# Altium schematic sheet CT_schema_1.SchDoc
size 641 x 498 mm
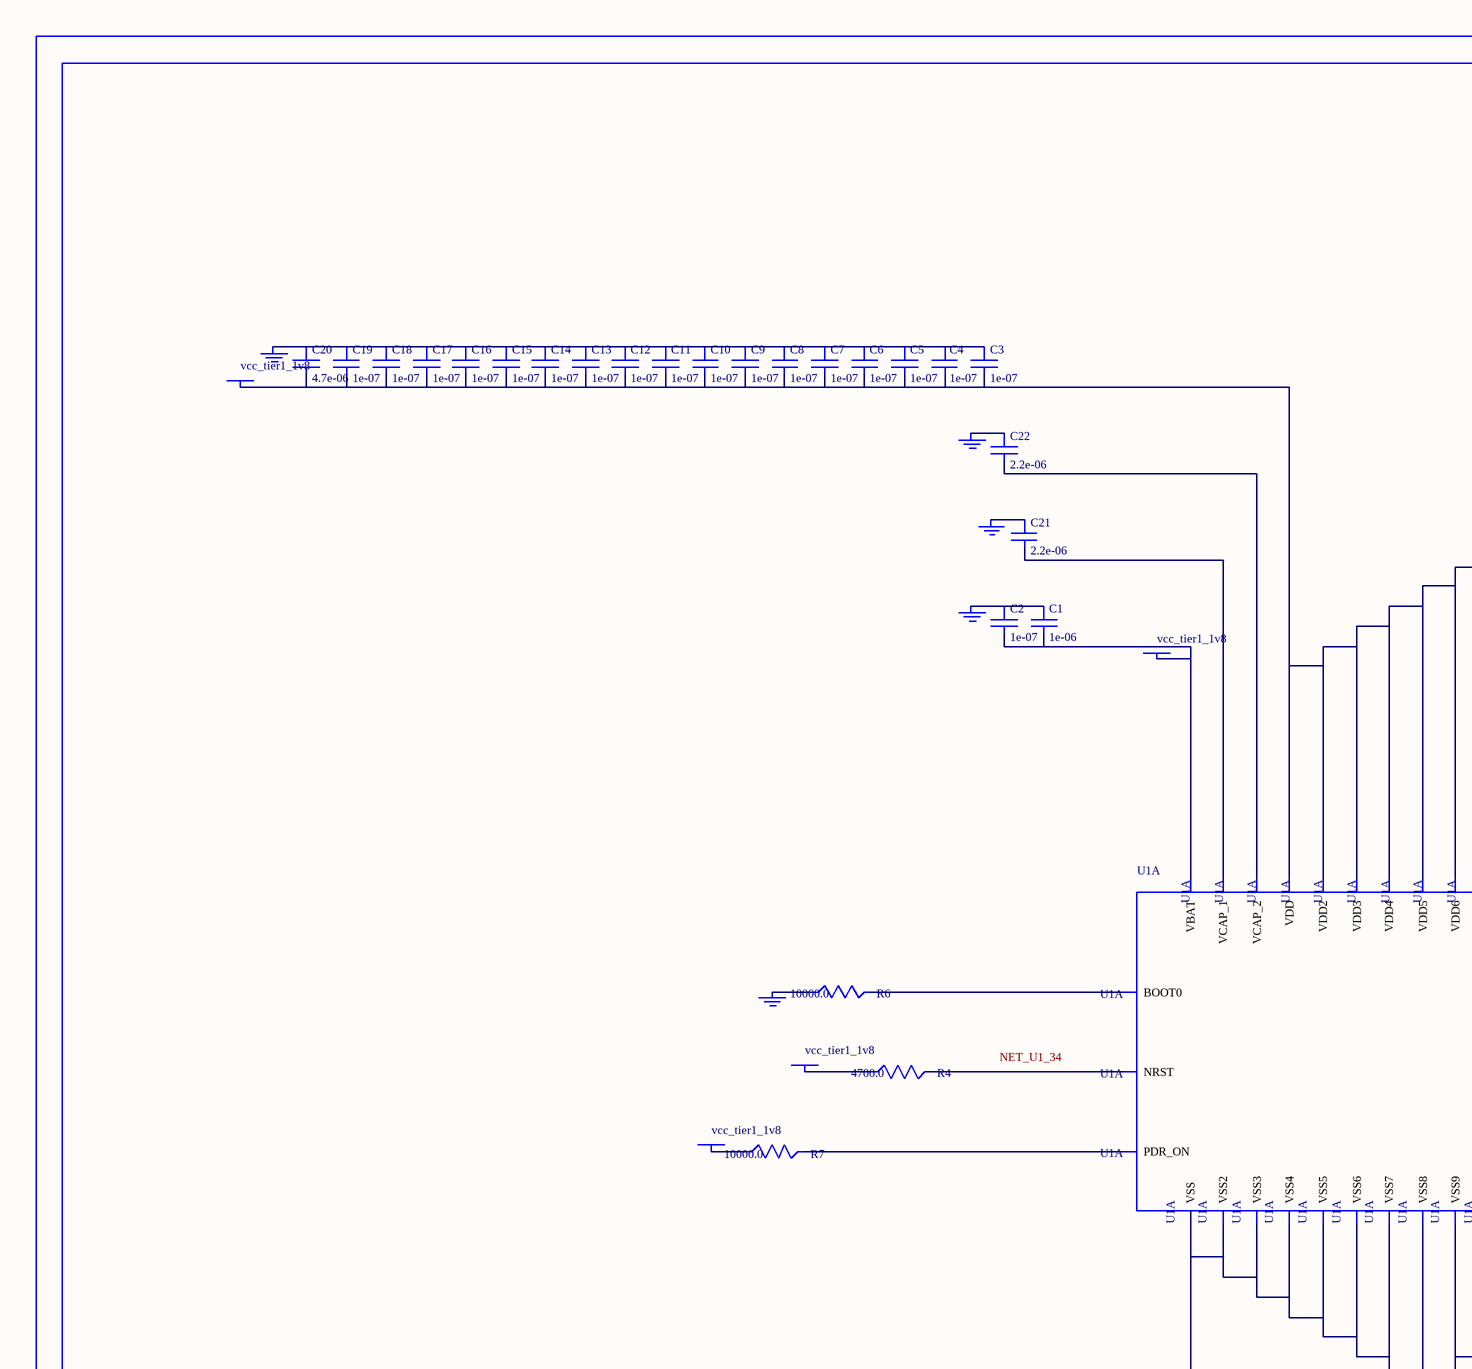
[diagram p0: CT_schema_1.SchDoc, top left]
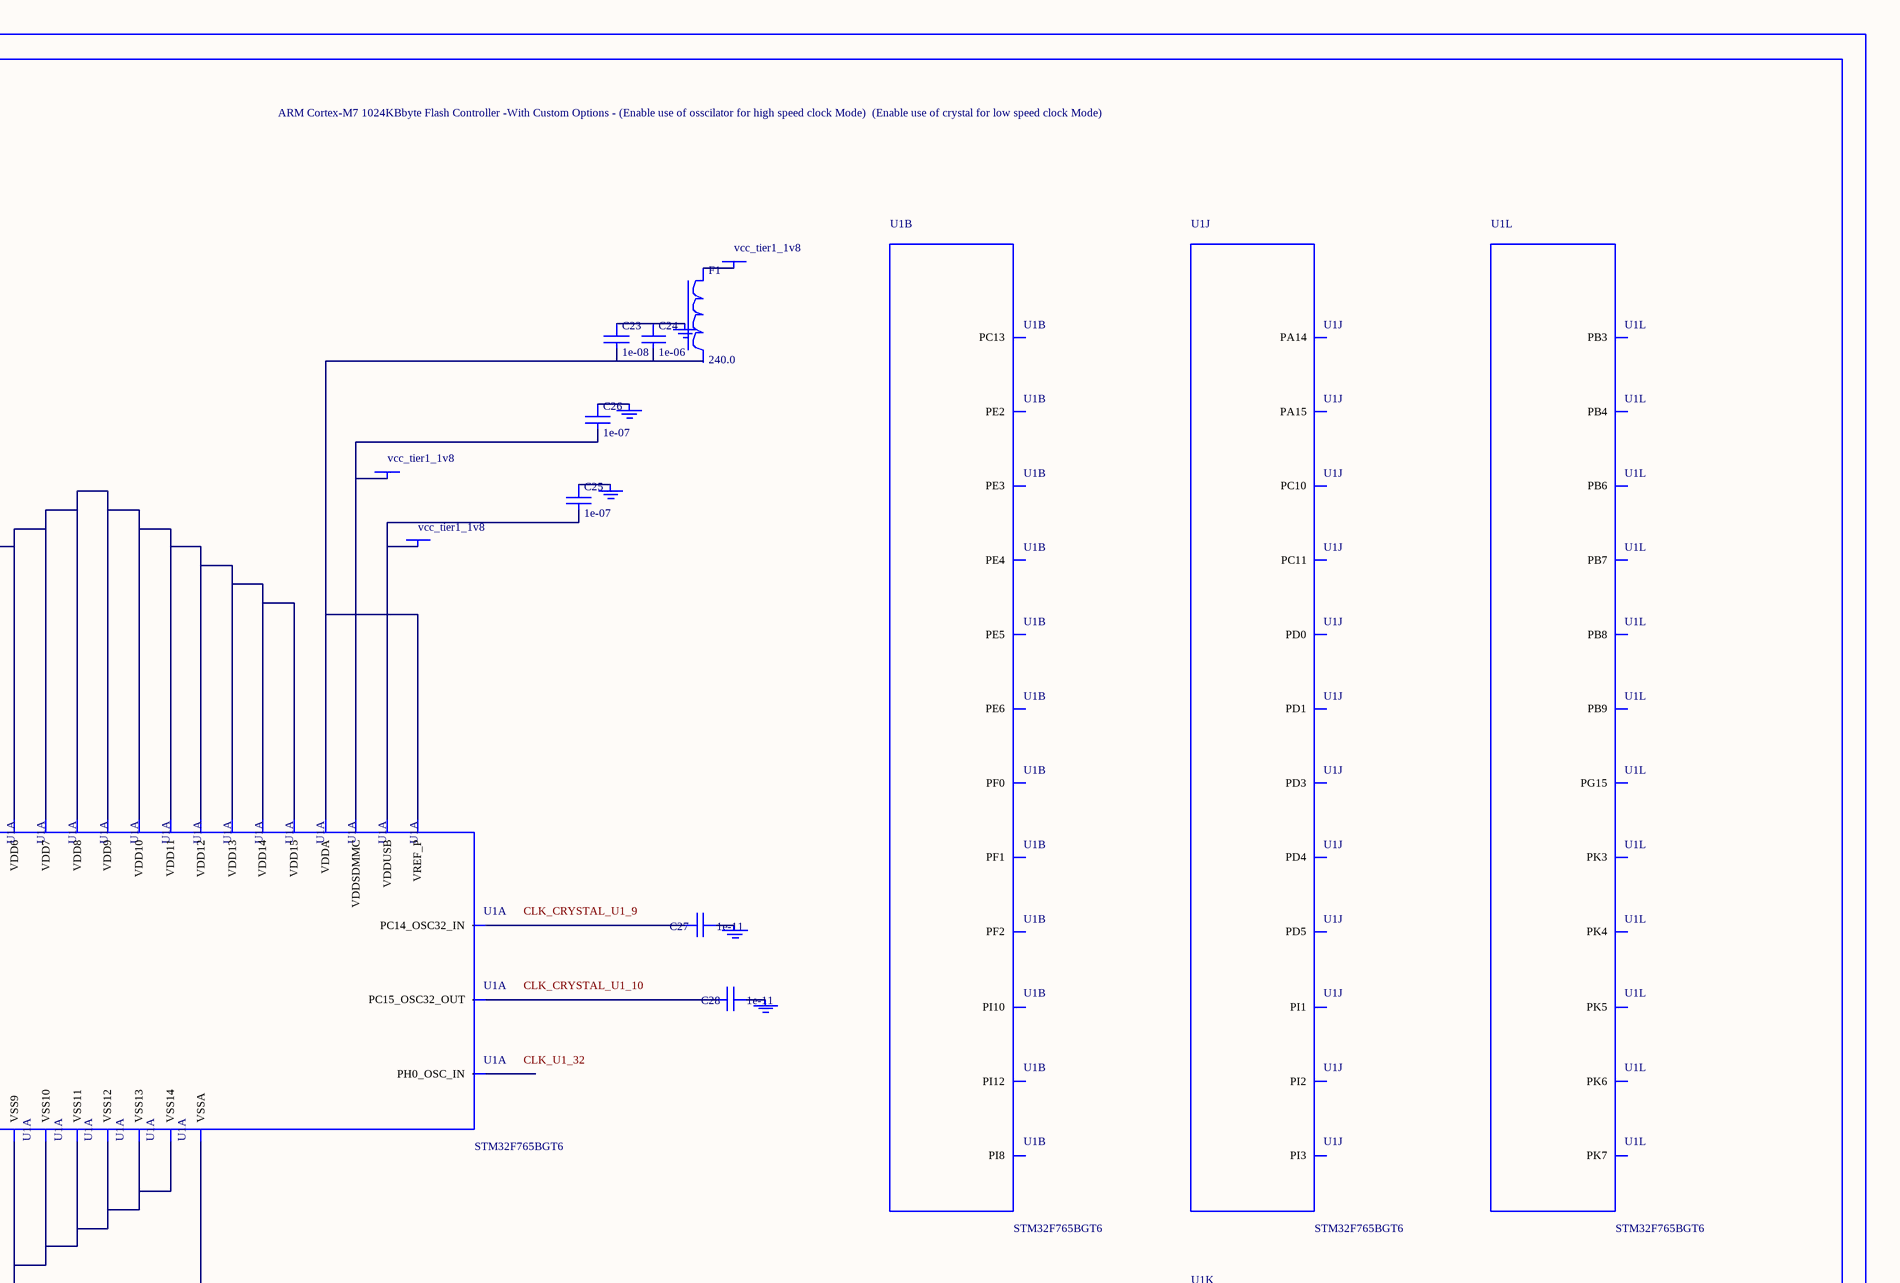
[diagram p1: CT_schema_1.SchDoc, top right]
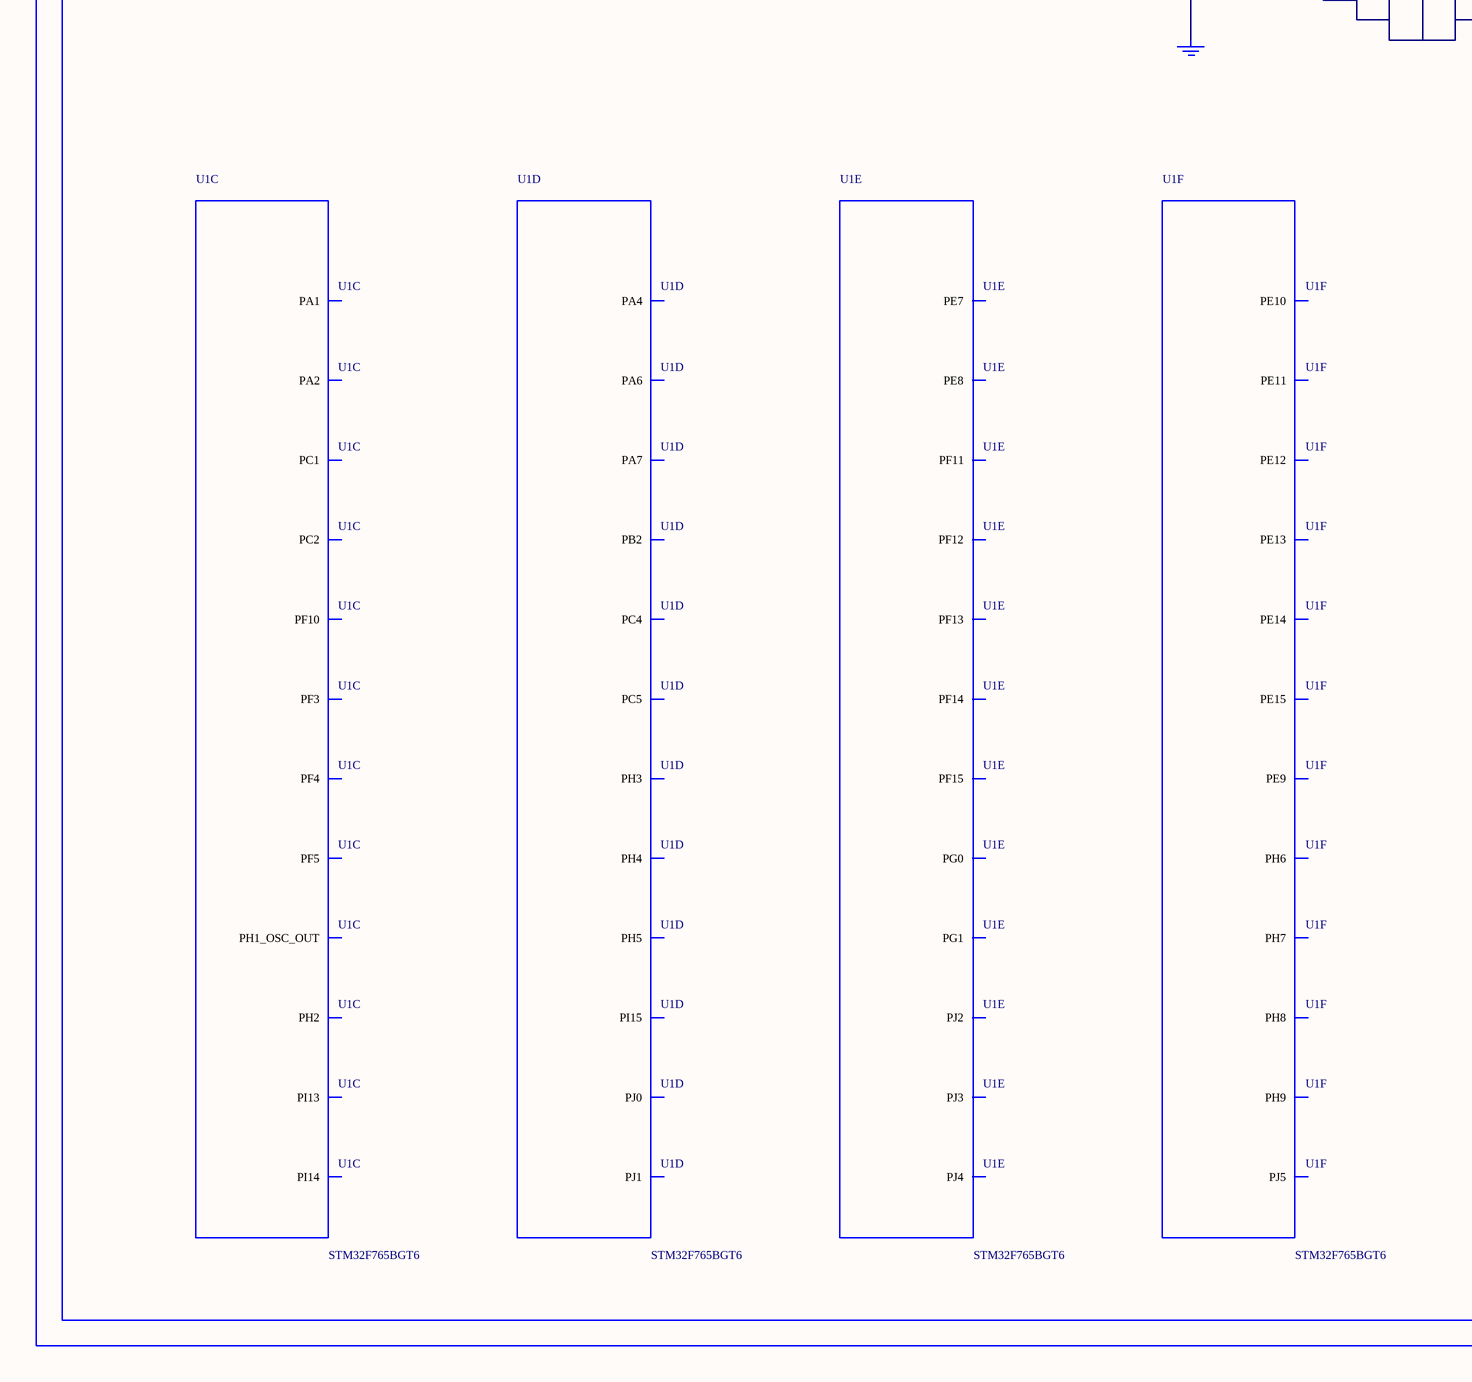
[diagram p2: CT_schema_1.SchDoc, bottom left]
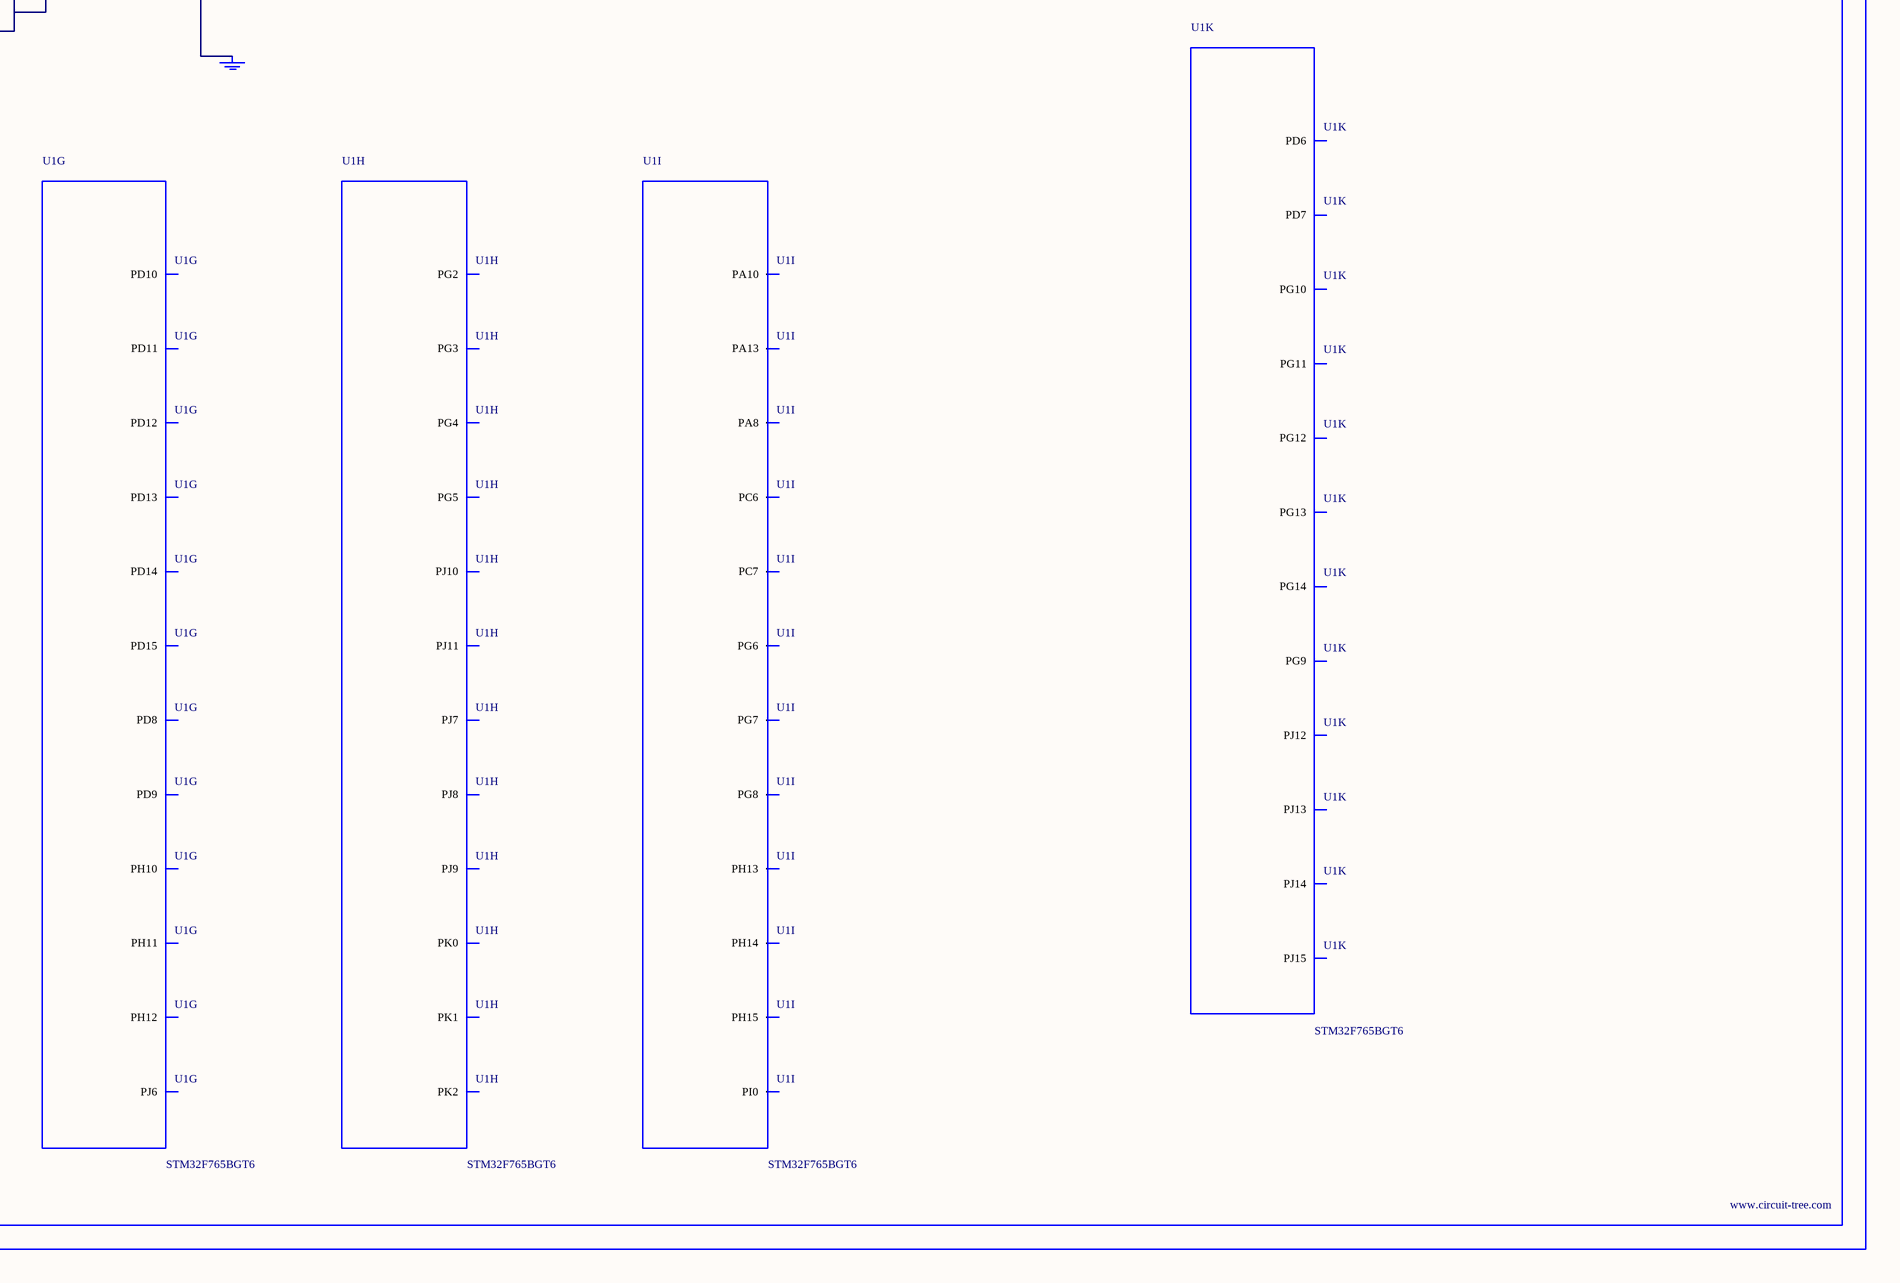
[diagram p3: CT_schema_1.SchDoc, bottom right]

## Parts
BORDER0  (no value)
C1  1e-06  [C0603]
C2  1e-07  [C0603]
C3  1e-07  [C0603]
C4  1e-07  [C0603]
C5  1e-07  [C0603]
C6  1e-07  [C0603]
C7  1e-07  [C0603]
C8  1e-07  [C0603]
C9  1e-07  [C0603]
C10  1e-07  [C0603]
C11  1e-07  [C0603]
C12  1e-07  [C0603]
C13  1e-07  [C0603]
C14  1e-07  [C0603]
C15  1e-07  [C0603]
C16  1e-07  [C0603]
C17  1e-07  [C0603]
C18  1e-07  [C0603]
C19  1e-07  [C0603]
C20  4.7e-06  [C0603]
C21  2.2e-06  [C0603]
C22  2.2e-06  [C0603]
C23  1e-08  [C0603]
C24  1e-06  [C0603]
C25  1e-07  [C0603]
C26  1e-07  [C0603]
C27  1e-11  [C0402]
C28  1e-11  [C0402]
F1  240.0  [L0603]
GND_INSTANCE_0_0  (no value)
GND_INSTANCE_0_1  (no value)
GND_INSTANCE_0_2  (no value)
GND_INSTANCE_0_3  (no value)
GND_INSTANCE_0_4  (no value)
GND_INSTANCE_0_5  (no value)
GND_INSTANCE_0_6  (no value)
GND_INSTANCE_0_7  (no value)
GND_INSTANCE_0_8  (no value)
GND_INSTANCE_0_9  (no value)
GND_INSTANCE_0_10  (no value)
GND_INSTANCE_0_11  (no value)
POWER_INSTANCE_0_0  vcc_tier1_1v8
POWER_INSTANCE_0_1  vcc_tier1_1v8
POWER_INSTANCE_0_2  vcc_tier1_1v8
POWER_INSTANCE_0_3  vcc_tier1_1v8
POWER_INSTANCE_0_4  vcc_tier1_1v8
POWER_INSTANCE_0_5  vcc_tier1_1v8
POWER_INSTANCE_0_6  vcc_tier1_1v8
R4  4700.0  [R0603]
R6  10000.0  [R0603]
R7  10000.0  [R0603]
U1  STM32F765BGT6  [LQFP208]  (parts A,B,C,D,E,F,G,H,I,J,K,L of 16)

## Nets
NetC1_1: C1.1 C2.1 GND_INSTANCE_0_0.0(GND)
NetC1_2: C1.2 C2.2 POWER_INSTANCE_0_0.0(PWR) U1.6(VBAT)
NetC3_1: C3.1 C4.1 C5.1 C6.1 C7.1 C8.1 C9.1 C10.1 C11.1 C12.1 C13.1 C14.1 C15.1 C16.1 C17.1 C18.1 C19.1 C20.1 GND_INSTANCE_0_3.0(GND)
NetC3_2: C3.2 C4.2 C5.2 C6.2 C7.2 C8.2 C9.2 C10.2 C11.2 C12.2 C13.2 C14.2 C15.2 C16.2 C17.2 C18.2 C19.2 C20.2 POWER_INSTANCE_0_1.0(PWR) U1.15(VDD) U1.26(VDD2) U1.39(VDD3) U1.52(VDD4) U1.59(VDD5) U1.73(VDD6) U1.83(VDD7) U1.94(VDD8) U1.103(VDD9) U1.115(VDD10) U1.124(VDD11) U1.150(VDD12) U1.158(VDD13) U1.185(VDD14) U1.204(VDD15)
NetC21_1: C21.1 GND_INSTANCE_0_6.0(GND)
NetC21_2: C21.2 U1.92(VCAP_1)
NetC22_1: C22.1 GND_INSTANCE_0_8.0(GND)
NetC22_2: C22.2 U1.148(VCAP_2)
NetC23_1: C23.1 C24.1 GND_INSTANCE_0_5.0(GND)
NetC23_2: C23.2 C24.2 U1.41(VREF_P) U1.42(VDDA)
NetC25_1: C25.1 GND_INSTANCE_0_7.0(GND)
NetC25_2: C25.2 POWER_INSTANCE_0_3.0(PWR) U1.137(VDDUSB)
NetC26_1: C26.1 GND_INSTANCE_0_9.0(GND)
NetC26_2: C26.2 POWER_INSTANCE_0_4.0(PWR) U1.171(VDDSDMMC)
NetC27_1: C27.1 GND_INSTANCE_0_1.0(GND)
NetC27_2: C27.2 U1.9(PC14_OSC32_IN)
NetC28_1: C28.1 GND_INSTANCE_0_2.0(GND)
NetC28_2: C28.2 U1.10(PC15_OSC32_OUT)
NetF1_1: F1.1 POWER_INSTANCE_0_2.0(PWR)
NetGND_INSTANCE_0_4_0: GND_INSTANCE_0_4.0(GND) U1.40(VSSA)
NetGND_INSTANCE_0_10_0: GND_INSTANCE_0_10.0(GND) R6.1
NetGND_INSTANCE_0_11_0: GND_INSTANCE_0_11.0(GND) U1.14(VSS) U1.25(VSS2) U1.51(VSS3) U1.60(VSS4) U1.72(VSS5) U1.82(VSS6) U1.93(VSS7) U1.114(VSS8) U1.125(VSS9) U1.136(VSS10) U1.149(VSS11) U1.170(VSS12) U1.184(VSS13) U1.202(VSS14)
NetPOWER_INSTANCE_0_5_0: POWER_INSTANCE_0_5.0(PWR) R7.1
NetPOWER_INSTANCE_0_6_0: POWER_INSTANCE_0_6.0(PWR) R4.1
NetR4_2: R4.2 U1.34(NRST)
NetR6_2: R6.2 U1.197(BOOT0)
NetR7_2: R7.2 U1.203(PDR_ON)

Not connected (* = marked no-connect by the designer): F1 2; U1 1(PE2) 2(PE3) 3(PE4) 4(PE5) 5(PE6) 7(PI8) 8(PC13) 12(PI10) 16(PF0) 17(PF1) 18(PF2) 19(PI12) 20(PI13) 21(PI14) 22(PF3) 23(PF4) 24(PF5) 31(PF10) 32(PH0_OSC_IN) 33(PH1_OSC_OUT) 36(PC1) 37(PC2) 44(PA1) 45(PA2) 46(PH2) 47(PH3) 48(PH4) 49(PH5) 53(PA4) 55(PA6) 56(PA7) 57(PC4) 58(PC5) 63(PB2) 64(PI15) 65(PJ0) 66(PJ1) 67(PJ2) 68(PJ3) 69(PJ4) 70(PF11) 71(PF12) 74(PF13) 75(PF14) 76(PF15) 77(PG0) 78(PG1) 79(PE7) 80(PE8) 81(PE9) 84(PE10) 85(PE11) 86(PE12) 87(PE13) 88(PE14) 89(PE15) 95(PJ5) 96(PH6) 97(PH7) 98(PH8) 99(PH9) 100(PH10) 101(PH11) 102(PH12) 108(PD8) 109(PD9) 110(PD10) 111(PD11) 112(PD12) 113(PD13) 116(PD14) 117(PD15) 118(PJ6) 119(PJ7) 120(PJ8) 121(PJ9) 122(PJ10) 123(PJ11) 126(PK0) 127(PK1) 128(PK2) 129(PG2) 130(PG3) 131(PG4) 132(PG5) 133(PG6) 134(PG7) 135(PG8) 138(PC6) 139(PC7) 142(PA8) 144(PA10) 147(PA13) 151(PH13) 152(PH14) 153(PH15) 154(PI0) 155(PI1) 156(PI2) 157(PI3) 159(PA14) 160(PA15) 161(PC10) 162(PC11) 164(PD0) 165(PD1) 167(PD3) 168(PD4) 169(PD5) 172(PD6) 173(PD7) 174(PJ12) 175(PJ13) 176(PJ14) 177(PJ15) 178(PG9) 179(PG10) 180(PG11) 181(PG12) 182(PG13) 183(PG14) 186(PK3) 187(PK4) 188(PK5) 189(PK6) 190(PK7) 191(PG15) 192(PB3) 193(PB4) 195(PB6) 196(PB7) 198(PB8) 199(PB9)

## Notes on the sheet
- Labels drawn without touching a wire or pin: CLK_CRYSTAL_U1_9, CLK_CRYSTAL_U1_10, CLK_U1_32, NET_U1_34

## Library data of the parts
BORDER0 = BORDER_PAGE0
C1 C24 = C0603C105K3RACTU
C2-C19 C25 C26 = 06035C104K4Z2A
C20 = GRM188R6YA475KE15D
C21 C22 = C0603C225K8RACTU
C23 = 06035C103K4Z2A
C27 C28 = C0402C100K3GACTU
F1 = Z0603C241ASMST
GND_INSTANCE_0_0-GND_INSTANCE_0_11 = GND
POWER_INSTANCE_0_0-POWER_INSTANCE_0_6 = PWR
R4 = RC0603JR-074K7L
R6 R7 = RC0603JR-0710KL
